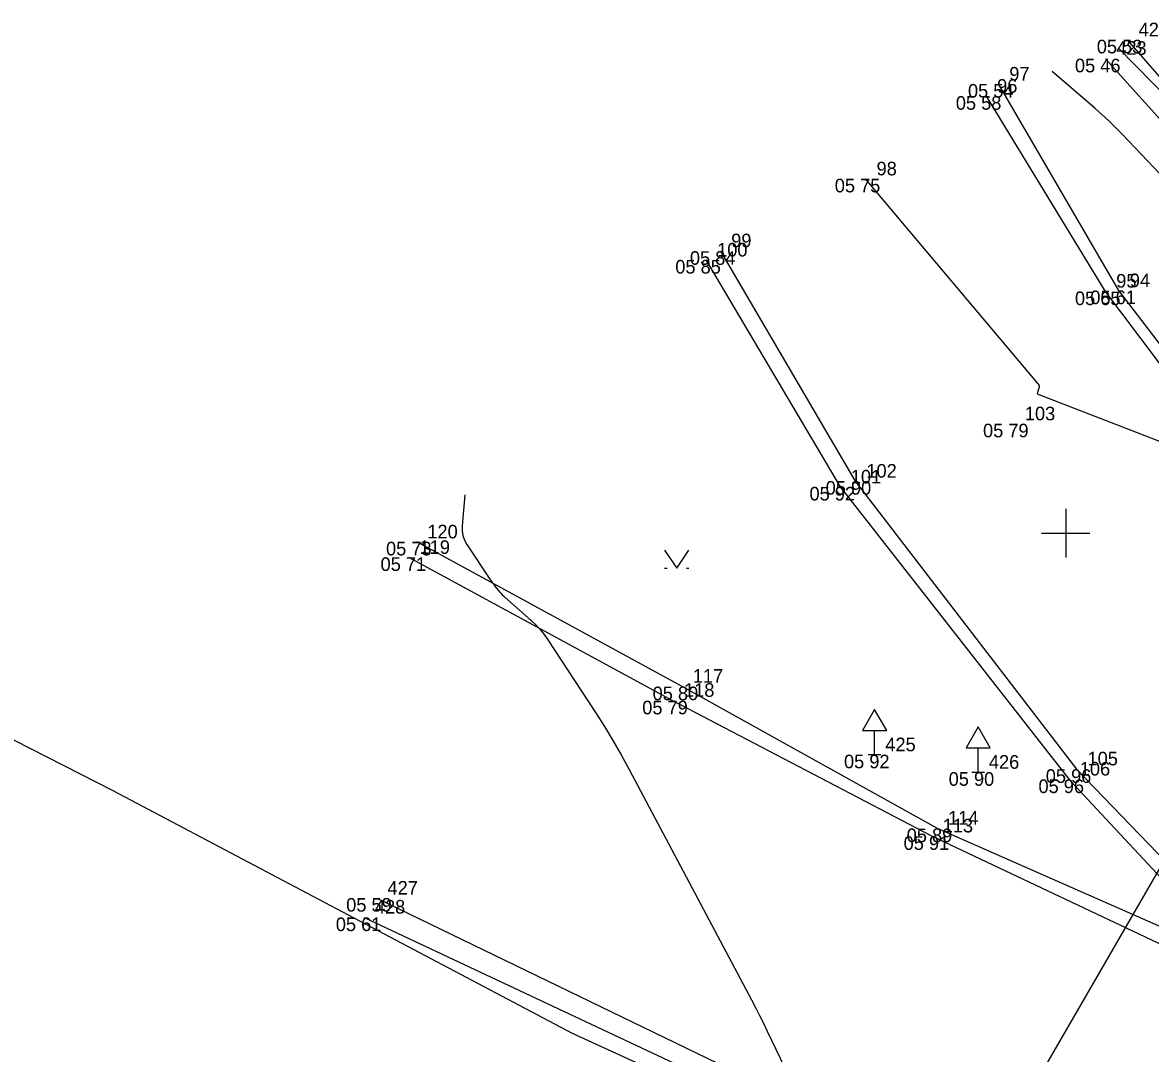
# Model space of a CAD drawing. Extents: x -711234 to -710007, y -1026313 to -1025448.
# Drawn here: x -711071.46 to -711048.26, y -1025885.71 to -1025864.5 of the extents above; entities that cross this region are included whole.
import ezdxf

# ---------------------------------------------------------------- set-up
doc = ezdxf.new("R2010")
doc.units = 0
for name, color, linetype in [('Ex_Minor Contours', 7, 'Continuous'), ('Z_body', 7, 'Continuous'), ('Z_body_cisla', 7, 'Continuous'), ('Z_body_vysky_redukovane', 7, 'Continuous'), ('Z_dopravni_znacky', 7, 'Continuous'), ('Z_hektometricka_sit', 7, 'Continuous'), ('Z_katastr_hranice', 7, 'Continuous'), ('Z_komunikace', 7, 'Continuous'), ('Z_propustek', 7, 'Continuous'), ('Z_vdz25_plna', 7, 'Continuous'), ('Z_zlabek', 7, 'Continuous'), ('Z_znaky_kultur', 7, 'Continuous')]:
    doc.layers.add(name, color=color, linetype=linetype)

# ---------------------------------------------------------------- blocks, each defined once
blk = doc.blocks.new('POINT_DISPLAY')
blk.add_line((0, 0), (0, 0))
blk = doc.blocks.new('Z527')
for p, q in [((0, 0.93), (-0.25, 0.5)), ((0.25, 0.5), (0, 0.93)), ((-0.25, 0.5), (0.25, 0.5)), ((0, 0), (0, 0.5)), ((-0.13, 0), (0.13, 0))]:
    blk.add_line(p, q)
blk = doc.blocks.new('Z314')
for p, q in [((-0.25, 0.17), (0, -0.2)), ((0, -0.2), (0.25, 0.17)), ((-0.25, -0.2), (-0.2, -0.2)), ((0.2, -0.2), (0.25, -0.2))]:
    blk.add_line(p, q)

msp = doc.modelspace()

# ---------------------------------------------------------------- linework, layer by layer
at = {"layer": 'Ex_Minor Contours'}
for points in [[(-711048.923, -1025865.017), (-711046.417, -1025867.569)], [(-711045.441, -1025870.368), (-711048.841, -1025866.793), (-711048.976, -1025866.654), (-711049.115, -1025866.519), (-711049.256, -1025866.387), (-711049.401, -1025866.259), (-711050.28, -1025865.5)], [(-711046.33, -1025873.791), (-711050.548, -1025872.157), (-711050.566, -1025872.148), (-711050.576, -1025872.135), (-711050.579, -1025872.118), (-711050.575, -1025872.099), (-711050.545, -1025872.015), (-711050.54, -1025871.994), (-711050.541, -1025871.975), (-711050.547, -1025871.956), (-711050.559, -1025871.939), (-711054.12, -1025867.71)], [(-711062.358, -1025874.213), (-711062.414, -1025874.849), (-711062.415, -1025874.953), (-711062.399, -1025875.052), (-711062.366, -1025875.148), (-711062.316, -1025875.238), (-711061.833, -1025875.967), (-711061.811, -1025875.999), (-711061.788, -1025876.03), (-711061.765, -1025876.061), (-711061.741, -1025876.091), (-711061.643, -1025876.21), (-711061.617, -1025876.24), (-711061.591, -1025876.268), (-711061.564, -1025876.295), (-711061.535, -1025876.321), (-711060.995, -1025876.799), (-711060.898, -1025876.89), (-711060.808, -1025876.987), (-711060.725, -1025877.089), (-711060.649, -1025877.198), (-711059.672, -1025878.69), (-711059.489, -1025878.978), (-711059.312, -1025879.27), (-711059.141, -1025879.566), (-711058.978, -1025879.866), (-711056.466, -1025884.602), (-711056.382, -1025884.762), (-711056.299, -1025884.924), (-711056.218, -1025885.086), (-711056.139, -1025885.249), (-711055.694, -1025886.174)]]:
    msp.add_lwpolyline(points, dxfattribs=at)
at = {"layer": 'Z_hektometricka_sit'}
for p, q in [((-711050, -1025874.5), (-711050, -1025875.5)), ((-711050.5, -1025875), (-711049.5, -1025875))]:
    msp.add_line(p, q, dxfattribs=at)
at = {"layer": 'Z_katastr_hranice'}
msp.add_lwpolyline([(-711143.66, -1025881.69), (-711119.52, -1025871.38), (-711081.1, -1025874.43), (-711069.6, -1025880.3), (-711060.15, -1025885.29), (-711049.51, -1025890.17), (-711031.09, -1025901.74), (-711010.7, -1025906.92), (-710992.71, -1025905.14), (-710973.48, -1025897.7)], dxfattribs=at)
at = {"layer": 'Z_komunikace'}
for p, q in [((-711048.91, -1025870.01), (-711051.38, -1025865.76)), ((-711057.4, -1025869.38), (-711054.64, -1025874.05)), ((-711045.08, -1025875.01), (-711048.91, -1025870.01)), ((-711054.64, -1025874.05), (-711049.93, -1025880.07)), ((-711057.89, -1025878.16), (-711063.35, -1025875.18)), ((-711052.64, -1025881.08), (-711057.89, -1025878.16)), ((-711049.93, -1025880.07), (-711047.22, -1025882.98)), ((-711047.49, -1025883.35), (-711052.64, -1025881.08)), ((-711064.43, -1025882.91), (-711056.04, -1025886.85))]:
    msp.add_line(p, q, dxfattribs=at)
at = {"layer": 'Z_propustek'}
msp.add_line((-711053.28, -1025890.92), (-711042.93, -1025873.02), dxfattribs=at)
at = {"layer": 'Z_vdz25_plna'}
for p, q in [((-711049.18, -1025870.03), (-711051.63, -1025866.01)), ((-711057.1, -1025869.2), (-711054.33, -1025873.93)), ((-711045.31, -1025875.18), (-711049.18, -1025870.03)), ((-711054.33, -1025873.93), (-711049.78, -1025879.86)), ((-711058.08, -1025878.45), (-711063.51, -1025875.5)), ((-711052.75, -1025881.24), (-711058.08, -1025878.45)), ((-711049.78, -1025879.86), (-711046.99, -1025882.75)), ((-711047.67, -1025883.64), (-711052.75, -1025881.24)), ((-711064.17, -1025882.51), (-711055.85, -1025886.54))]:
    msp.add_line(p, q, dxfattribs=at)
at = {"layer": 'Z_zlabek'}
for p, q in [((-711044.05, -1025870.22), (-711048.73, -1025864.85)), ((-711044.32, -1025870.65), (-711049.18, -1025865.24))]:
    msp.add_line(p, q, dxfattribs=at)

# ---------------------------------------------------------------- block references
at = {"layer": 'Z_body'}
for p in [(-711048.73, -1025864.85), (-711049.18, -1025865.24), (-711051.38, -1025865.76), (-711051.63, -1025866.01), (-711054.12, -1025867.71), (-711057.4, -1025869.38), (-711057.1, -1025869.2), (-711049.18, -1025870.03), (-711048.91, -1025870.01), (-711051.07, -1025872.75), (-711054.64, -1025874.05), (-711054.33, -1025873.93), (-711063.35, -1025875.18), (-711063.51, -1025875.5), (-711057.89, -1025878.16), (-711058.08, -1025878.45), (-711053.93, -1025879.56), (-711051.8, -1025879.92), (-711049.93, -1025880.07), (-711049.78, -1025879.86), (-711052.75, -1025881.24), (-711052.64, -1025881.08), (-711064.17, -1025882.51), (-711064.43, -1025882.91)]:
    msp.add_blockref('POINT_DISPLAY', p, dxfattribs=at)
at = {"layer": 'Z_dopravni_znacky'}
for p in [(-711053.93, -1025879.56), (-711051.8, -1025879.92)]:
    msp.add_blockref('Z527', p, dxfattribs=at)
at = {"layer": 'Z_znaky_kultur'}
msp.add_blockref('Z314', (-711058, -1025875.52), dxfattribs=at)

# ---------------------------------------------------------------- texts
at = {"layer": 'Z_body_cisla'}
for s, p in [('424', (-711048.5, -1025864.78)), ('423', (-711048.96, -1025865.16)), ('97', (-711051.16, -1025865.69)), ('96', (-711051.41, -1025865.94)), ('98', (-711053.89, -1025867.64)), ('99', (-711056.88, -1025869.12)), ('100', (-711057.17, -1025869.31)), ('95', (-711048.96, -1025869.95)), ('94', (-711048.68, -1025869.94)), ('103', (-711050.84, -1025872.68)), ('102', (-711054.1, -1025873.86)), ('101', (-711054.42, -1025873.98)), ('120', (-711063.13, -1025875.11)), ('119', (-711063.29, -1025875.43)), ('117', (-711057.67, -1025878.08)), ('118', (-711057.85, -1025878.37)), ('425', (-711053.71, -1025879.49)), ('426', (-711051.58, -1025879.85)), ('105', (-711049.55, -1025879.78)), ('106', (-711049.71, -1025879.99)), ('114', (-711052.42, -1025881)), ('113', (-711052.53, -1025881.16)), ('427', (-711063.95, -1025882.44)), ('428', (-711064.21, -1025882.83))]:
    msp.add_text(s, height=0.28, dxfattribs=at).set_placement(p)
at = {"layer": 'Z_body_vysky_redukovane'}
for s, p in [('05 53', (-711049.36, -1025865.13)), ('05 46', (-711049.81, -1025865.52)), ('05 54', (-711052.01, -1025866.04)), ('05 58', (-711052.26, -1025866.29)), ('05 75', (-711054.75, -1025867.99)), ('05 85', (-711058.03, -1025869.66)), ('05 84', (-711057.73, -1025869.48)), ('05 65', (-711049.81, -1025870.31)), ('05 61', (-711049.493, -1025870.29)), ('05 79', (-711051.7, -1025873.03)), ('05 92', (-711055.27, -1025874.33)), ('05 90', (-711054.937, -1025874.21)), ('05 73', (-711063.98, -1025875.46)), ('05 71', (-711064.093, -1025875.78)), ('05 80', (-711058.497, -1025878.44)), ('05 79', (-711058.71, -1025878.73)), ('05 92', (-711054.56, -1025879.84)), ('05 96', (-711050.41, -1025880.14)), ('05 90', (-711052.407, -1025880.2)), ('05 96', (-711050.56, -1025880.35)), ('05 91', (-711053.333, -1025881.52)), ('05 89', (-711053.27, -1025881.36)), ('05 59', (-711064.8, -1025882.79)), ('05 61', (-711065.013, -1025883.19))]:
    msp.add_text(s, height=0.28, dxfattribs=at).set_placement(p)

doc.saveas('drawing.dxf')
